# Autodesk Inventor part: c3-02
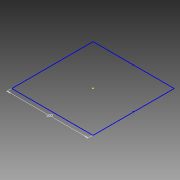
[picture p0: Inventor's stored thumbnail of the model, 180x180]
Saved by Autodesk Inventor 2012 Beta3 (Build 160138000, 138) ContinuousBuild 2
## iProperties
Created: 2010-11
Part Number: c3-02
Material: Default
Document SubType Name: Modeling
Designer: Beta-8540w
Density: 1 g/cm^3
Author: Beta-8540w
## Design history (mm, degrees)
sketch "Sketch1"
  geometry: L1 (-50, -50)-(50, -50); L2 (50, -50)-(50, 50); L3 (50, 50)-(-50, 50); L4 (-50, 50)-(-50, -50); 3 further points
  constraints: 8 end point, 3 perpendicular, 2 midpoint, 1 horizontal, 1 horizontal alignment, 1 parallel, 1 vertical alignment
  dimensions: "Width" = 100 dimension on point (0, 0) L1.start L1.end L1 L2.end L2 L3.end L3 L4 point (50, 0) point (0, 50); "Width" = 100 distance of L1.start L1.end
